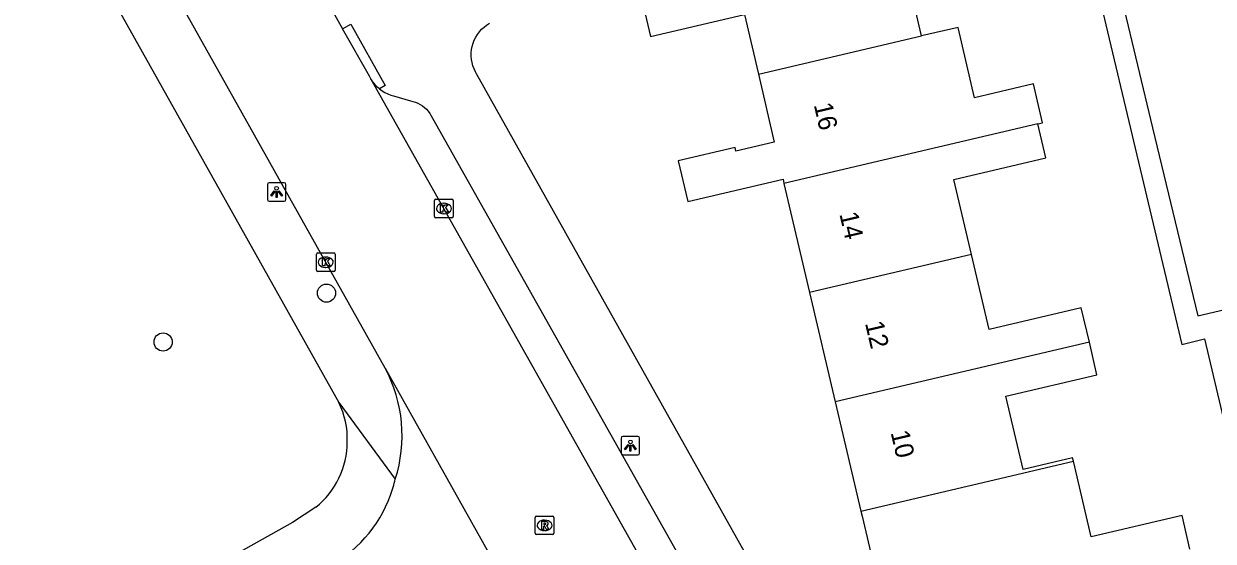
# Model space of a CAD drawing. Extents: x 158038 to 159242, y 380133 to 381214.
# Drawn here: x 158790.6 to 158854.6, y 380607.2 to 380635 of the extents above; entities that cross this region are included whole.
import ezdxf

# ---------------------------------------------------------------- set-up
doc = ezdxf.new("R2010")
doc.units = 0
for name, color, linetype in [('IMGEO_Boom', 7, 'Continuous'), ('IMGEO_Kolk', 7, 'Continuous'), ('IMGEO_Lichtpunt', 7, 'Continuous'), ('IMGEO_Pand', 7, 'Continuous'), ('IMGEO_Pand_nummerreeks', 7, 'Continuous'), ('IMGEO_Rijbaan_lokaal_gesloten', 7, 'Continuous'), ('IMGEO_Rijbaan_lokaal_open', 7, 'Continuous'), ('IMGEO_Rioolput', 7, 'Continuous'), ('IMGEO_Voetpad_open', 7, 'Continuous')]:
    doc.layers.add(name, color=color, linetype=linetype)

msp = doc.modelspace()

# ---------------------------------------------------------------- linework, layer by layer
at = {"layer": 'IMGEO_Boom'}
for centre in [(158806.869, 380620.52), (158798.082, 380617.889)]:
    msp.add_circle(centre, 0.489, dxfattribs=at)
at = {"layer": 'IMGEO_Kolk'}
for p, q in [((158812.681, 380624.647), (158812.681, 380625.499)), ((158812.756, 380625.573), (158813.608, 380625.573)), ((158813.169, 380625.353), (158813.194, 380625.353)), ((158813.682, 380625.499), (158813.682, 380624.647)), ((158813.608, 380624.573), (158812.756, 380624.573)), ((158813.192, 380624.793), (158813.167, 380624.793)), ((158806.405, 380622.682), (158807.257, 380622.682)), ((158806.33, 380621.756), (158806.33, 380622.608)), ((158806.818, 380622.462), (158806.843, 380622.462)), ((158807.331, 380622.608), (158807.331, 380621.756)), ((158807.257, 380621.682), (158806.405, 380621.682)), ((158806.841, 380621.902), (158806.816, 380621.902))]:
    msp.add_line(p, q, dxfattribs=at)
for points in [[(158812.681, 380624.647), (158812.681, 380625.499)], [(158812.756, 380625.573), (158813.608, 380625.573)], [(158813.002, 380625.273), (158813.125, 380625.273), (158813.125, 380625.122), (158813.255, 380625.273), (158813.419, 380625.273), (158813.273, 380625.122), (158813.426, 380624.873), (158813.274, 380624.873), (158813.189, 380625.037), (158813.125, 380624.97), (158813.125, 380624.873), (158813.002, 380624.873), (158813.002, 380625.273)], [(158813.682, 380625.499), (158813.682, 380624.647)], [(158813.608, 380624.573), (158812.756, 380624.573)], [(158806.405, 380622.682), (158807.257, 380622.682)], [(158806.33, 380621.756), (158806.33, 380622.608)], [(158806.651, 380622.382), (158806.774, 380622.382), (158806.774, 380622.231), (158806.904, 380622.382), (158807.068, 380622.382), (158806.922, 380622.231), (158807.075, 380621.982), (158806.923, 380621.982), (158806.838, 380622.146), (158806.774, 380622.079), (158806.774, 380621.982), (158806.651, 380621.982), (158806.651, 380622.382)], [(158807.331, 380622.608), (158807.331, 380621.756)], [(158807.257, 380621.682), (158806.405, 380621.682)]]:
    msp.add_lwpolyline(points, dxfattribs=at)
for centre, start, end in [((158812.758, 380625.497), 91.55205, 178.44795), ((158812.758, 380625.497), 91.55205, 178.44795), ((158813.606, 380625.497), 1.55205, 88.44795), ((158813.606, 380625.497), 1.55205, 88.44795), ((158812.758, 380624.649), 181.55205, 268.44795), ((158812.758, 380624.649), 181.55205, 268.44795), ((158813.606, 380624.649), 271.55205, 358.44795), ((158813.606, 380624.649), 271.55205, 358.44795), ((158806.407, 380622.606), 91.55205, 178.44795), ((158806.407, 380622.606), 91.55205, 178.44795), ((158807.255, 380622.606), 1.55205, 88.44795), ((158807.255, 380622.606), 1.55205, 88.44795), ((158806.407, 380621.758), 181.55205, 268.44795), ((158806.407, 380621.758), 181.55205, 268.44795), ((158807.255, 380621.758), 271.55205, 358.44795), ((158807.255, 380621.758), 271.55205, 358.44795)]:
    msp.add_arc(centre, 0.0765, start, end, dxfattribs=at)
for centre, major_axis, ratio, start_param, end_param in [((158813.168, 380625.073), (-0.387, 0.002), 0.722429, 4.712389, 7.853982), ((158813.193, 380625.073), (-0.39, 0.002), 0.717154, 1.570796, 4.712389), ((158806.817, 380622.182), (-0.387, 0.002), 0.722429, 4.712389, 7.853982), ((158806.842, 380622.182), (-0.39, 0.002), 0.717154, 1.570796, 4.712389)]:
    msp.add_ellipse(centre, major_axis=major_axis, ratio=ratio, start_param=start_param, end_param=end_param, dxfattribs=at)
at = {"layer": 'IMGEO_Lichtpunt'}
for p, q in [((158804.591, 380626.458), (158803.783, 380626.458)), ((158804.591, 380626.458), (158803.783, 380626.458)), ((158803.689, 380626.363), (158803.689, 380625.556)), ((158803.689, 380626.363), (158803.689, 380625.556)), ((158804.685, 380625.556), (158804.685, 380626.363)), ((158804.685, 380625.556), (158804.685, 380626.363)), ((158803.783, 380625.462), (158804.591, 380625.462)), ((158803.783, 380625.462), (158804.591, 380625.462)), ((158822.713, 380612.717), (158822.713, 380611.91)), ((158822.713, 380612.717), (158822.713, 380611.91)), ((158823.615, 380612.812), (158822.807, 380612.812)), ((158823.615, 380612.812), (158822.807, 380612.812)), ((158823.709, 380611.91), (158823.709, 380612.717)), ((158823.709, 380611.91), (158823.709, 380612.717)), ((158822.807, 380611.816), (158823.615, 380611.816)), ((158822.807, 380611.816), (158823.615, 380611.816))]:
    msp.add_line(p, q, dxfattribs=at)
for points in [[(158804.063, 380626.027), (158804.102, 380625.999), (158803.914, 380625.737), (158803.876, 380625.764), (158804.063, 380626.027)], [(158804.165, 380625.979), (158804.212, 380625.979), (158804.212, 380625.657), (158804.165, 380625.657), (158804.165, 380625.979)], [(158804.275, 380625.999), (158804.313, 380626.026), (158804.5, 380625.764), (158804.461, 380625.736), (158804.275, 380625.999)], [(158823.087, 380612.381), (158823.126, 380612.353), (158822.938, 380612.091), (158822.9, 380612.118), (158823.087, 380612.381)], [(158823.299, 380612.353), (158823.337, 380612.38), (158823.524, 380612.118), (158823.485, 380612.09), (158823.299, 380612.353)], [(158823.189, 380612.333), (158823.236, 380612.333), (158823.236, 380612.011), (158823.189, 380612.011), (158823.189, 380612.333)]]:
    msp.add_lwpolyline(points, dxfattribs=at)
for centre in [(158804.188, 380626.161), (158823.212, 380612.515)]:
    msp.add_circle(centre, 0.0994, dxfattribs=at)
for centre, start, end in [((158803.783, 380626.363), 90, 180), ((158803.783, 380626.363), 90, 180), ((158804.591, 380626.363), 0, 90), ((158804.591, 380626.363), 0, 90), ((158803.783, 380625.556), 180, 270), ((158803.783, 380625.556), 180, 270), ((158804.591, 380625.556), 270, 0), ((158804.591, 380625.556), 270, 360), ((158822.807, 380612.717), 90, 180), ((158822.807, 380612.717), 90, 180), ((158823.615, 380612.717), 0, 90), ((158823.615, 380612.717), 0, 90), ((158822.807, 380611.91), 180, 270), ((158822.807, 380611.91), 180, 270), ((158823.615, 380611.91), 270, 0), ((158823.615, 380611.91), 270, 360)]:
    msp.add_arc(centre, 0.0946, start, end, dxfattribs=at)
at = {"layer": 'IMGEO_Pand'}
for points in [[(158838.871, 380634.359), (158837.913, 380638.445), (158839.404, 380638.794), (158838.947, 380640.743)], [(158823.639, 380637.155), (158824.302, 380634.327), (158829.344, 380635.508), (158830.095, 380632.302)], [(158845.124, 380629.627), (158845.384, 380629.688), (158844.895, 380631.776), (158841.726, 380631.033), (158840.838, 380634.82), (158838.871, 380634.359)], [(158830.095, 380632.302), (158838.871, 380634.359)], [(158830.095, 380632.302), (158830.952, 380628.644), (158828.888, 380628.16), (158828.842, 380628.355), (158825.785, 380627.639), (158826.298, 380625.448), (158831.42, 380626.648), (158831.472, 380626.426)], [(158845.124, 380629.627), (158831.472, 380626.426)], [(158841.563, 380622.591), (158840.614, 380626.641), (158845.552, 380627.799), (158845.124, 380629.627)], [(158831.472, 380626.426), (158832.85, 380620.548)], [(158841.563, 380622.591), (158832.85, 380620.548)], [(158847.895, 380617.876), (158847.462, 380619.723), (158842.507, 380618.562), (158841.563, 380622.591)], [(158832.85, 380620.548), (158834.227, 380614.671)], [(158847.895, 380617.876), (158834.227, 380614.671)], [(158847.038, 380611.477), (158846.995, 380611.661), (158844.334, 380611.037), (158843.411, 380614.974), (158848.306, 380616.121), (158847.895, 380617.876)], [(158834.227, 380614.671), (158835.604, 380608.795)], [(158835.604, 380608.795), (158847.038, 380611.477)], [(158853.303, 380606.745), (158852.879, 380608.553), (158847.992, 380607.407), (158847.038, 380611.477)], [(158835.604, 380608.795), (158835.671, 380608.511), (158836.982, 380602.918)]]:
    msp.add_lwpolyline(points, dxfattribs=at)
at = {"layer": 'IMGEO_Rijbaan_lokaal_gesloten'}
for points in [[(158810.02, 380616.484), (158772.877, 380682.742)], [(158807.225, 380635.635), (158807.733, 380634.738)], [(158809.256, 380632.041), (158809.177, 380632.187), (158807.733, 380634.738)], [(158836.527, 380583.492), (158836.306, 380583.892), (158824.26, 380605.383), (158809.591, 380631.446), (158809.256, 380632.041)], [(158810.02, 380616.484), (158820.231, 380598.271)]]:
    msp.add_lwpolyline(points, dxfattribs=at)
at = {"layer": 'IMGEO_Rijbaan_lokaal_open'}
for centre, radius, start, end in [((158803.264, 380612.848), 7.672, 342.22431, 28.28897), ((158803.388, 380612.182), 7.375, 339.90629, 346.86684), ((158803.537, 380612.139), 7.221, 297.02872, 339.81981)]:
    msp.add_arc(centre, radius, start, end, dxfattribs=at)
at = {"layer": 'IMGEO_Rioolput'}
for p, q in [((158818.095, 380607.599), (158818.095, 380608.451)), ((158818.17, 380608.525), (158819.022, 380608.525)), ((158818.583, 380608.305), (158818.608, 380608.305)), ((158819.096, 380608.451), (158819.096, 380607.599)), ((158819.022, 380607.525), (158818.17, 380607.525)), ((158818.606, 380607.745), (158818.581, 380607.745))]:
    msp.add_line(p, q, dxfattribs=at)
for points in [[(158818.095, 380607.599), (158818.095, 380608.451)], [(158818.17, 380608.525), (158819.022, 380608.525)], [(158818.684, 380608.223), (158818.432, 380608.225), (158818.432, 380607.825)], [(158818.432, 380607.825), (158818.556, 380607.825), (158818.556, 380607.987), (158818.567, 380607.987)], [(158818.61, 380608.144), (158818.556, 380608.144), (158818.556, 380608.063)], [(158818.556, 380608.063), (158818.608, 380608.063)], [(158818.614, 380607.958), (158818.685, 380607.825), (158818.825, 380607.825), (158818.76, 380607.951)], [(158819.096, 380608.451), (158819.096, 380607.599)], [(158819.022, 380607.525), (158818.17, 380607.525)]]:
    msp.add_lwpolyline(points, dxfattribs=at)
for centre, radius, start, end in [((158818.172, 380608.449), 0.0765, 91.55205, 178.44795), ((158818.172, 380608.449), 0.0765, 91.55205, 178.44795), ((158818.566, 380607.934), 0.0533, 26.02933, 88.69889), ((158818.592, 380608.252), 0.19, 274.7715, 282.96867), ((158818.616, 380608.048), 0.0964, 77.00612, 93.18647), ((158818.63, 380608.105), 0.0378, 276.66336, 79.67722), ((158818.683, 380608.113), 0.109, 350.36119, 89.41601), ((158818.681, 380608.113), 0.112, 277.58423, 350.98172), ((158818.665, 380607.898), 0.108, 29.51342, 73.79051), ((158819.02, 380608.449), 0.0765, 1.55205, 88.44795), ((158819.02, 380608.449), 0.0765, 1.55205, 88.44795), ((158818.172, 380607.601), 0.0765, 181.55205, 268.44795), ((158818.172, 380607.601), 0.0765, 181.55205, 268.44795), ((158819.02, 380607.601), 0.0765, 271.55205, 358.44795), ((158819.02, 380607.601), 0.0765, 271.55205, 358.44795)]:
    msp.add_arc(centre, radius, start, end, dxfattribs=at)
for centre, major_axis, ratio, start_param, end_param in [((158818.582, 380608.025), (-0.387, 0.002), 0.722429, 4.712389, 7.853982), ((158818.607, 380608.025), (-0.39, 0.002), 0.717154, 1.570796, 4.712389)]:
    msp.add_ellipse(centre, major_axis=major_axis, ratio=ratio, start_param=start_param, end_param=end_param, dxfattribs=at)
at = {"layer": 'IMGEO_Voetpad_open'}
for points in [[(158769.672, 380682.252), (158793.972, 380638.844), (158795.053, 380636.914), (158807.529, 380614.627)], [(158846.953, 380642.661), (158852.026, 380621.299), (158852.866, 380617.761), (158854.089, 380618.052), (158855.186, 380613.434), (158856.693, 380613.792), (158858.635, 380605.618), (158860.85, 380596.288)], [(158848.057, 380642.926), (158851.295, 380629.411), (158853.72, 380619.292), (158855.175, 380619.641), (158856.318, 380614.873), (158857.817, 380615.232), (158862.246, 380596.596)], [(158807.733, 380634.738), (158808.17, 380634.984), (158810.026, 380631.691), (158809.712, 380631.514)], [(158842.019, 380583.982), (158814.933, 380632.324), (158814.876, 380632.426), (158814.802, 380632.586), (158814.742, 380632.752), (158814.697, 380632.922), (158814.667, 380633.097), (158814.653, 380633.273), (158814.655, 380633.449), (158814.673, 380633.625), (158814.706, 380633.798), (158814.755, 380633.968), (158814.819, 380634.133), (158814.897, 380634.291), (158814.989, 380634.442), (158815.094, 380634.584), (158815.211, 380634.716), (158815.34, 380634.837), (158815.479, 380634.946), (158815.627, 380635.042)], [(158809.712, 380631.514), (158809.585, 380631.626), (158809.463, 380631.754), (158809.353, 380631.893), (158809.256, 380632.041)], [(158809.712, 380631.514), (158809.86, 380631.405), (158810.012, 380631.313), (158810.171, 380631.236), (158810.336, 380631.173), (158810.469, 380631.134), (158811.395, 380630.866), (158811.52, 380630.838), (158811.655, 380630.794), (158811.786, 380630.739), (158811.912, 380630.672), (158812.031, 380630.594), (158812.143, 380630.506), (158812.247, 380630.409), (158812.341, 380630.302), (158812.425, 380630.187), (158812.499, 380630.066), (158812.562, 380629.938), (158836.462, 380587.488)], [(158807.529, 380614.627), (158810.57, 380610.506)], [(158806.29, 380609.007), (158805.037, 380608.18), (158783.016, 380595.835), (158781.538, 380595.008), (158766.939, 380586.844)]]:
    msp.add_lwpolyline(points, dxfattribs=at)
for centre, radius, start, end in [((158803.76, 380612.711), 4.228, 357.43009, 26.95258), ((158803.527, 380612.504), 4.457, 308.30774, 0.21746)]:
    msp.add_arc(centre, radius, start, end, dxfattribs=at)

# ---------------------------------------------------------------- texts
at = {"layer": 'IMGEO_Pand_nummerreeks'}
for s, p in [('16', (158833.069, 380630.655)), ('14', (158834.447, 380624.779)), ('12', (158835.824, 380618.905)), ('10', (158837.202, 380613.022))]:
    msp.add_text(s, height=1, rotation=283.19084, dxfattribs=at).set_placement(p)

doc.saveas('drawing.dxf')
